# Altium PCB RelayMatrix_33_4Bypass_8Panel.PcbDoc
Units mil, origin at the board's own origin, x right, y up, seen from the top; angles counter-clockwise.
Board outline 13300 x 7975 mil, 4 copper layers (Top Layer, GND, Layer 1, Bottom Layer), stack 60.556 mil thick; 0 components, 0 nets, 45 pads, 0 vias.
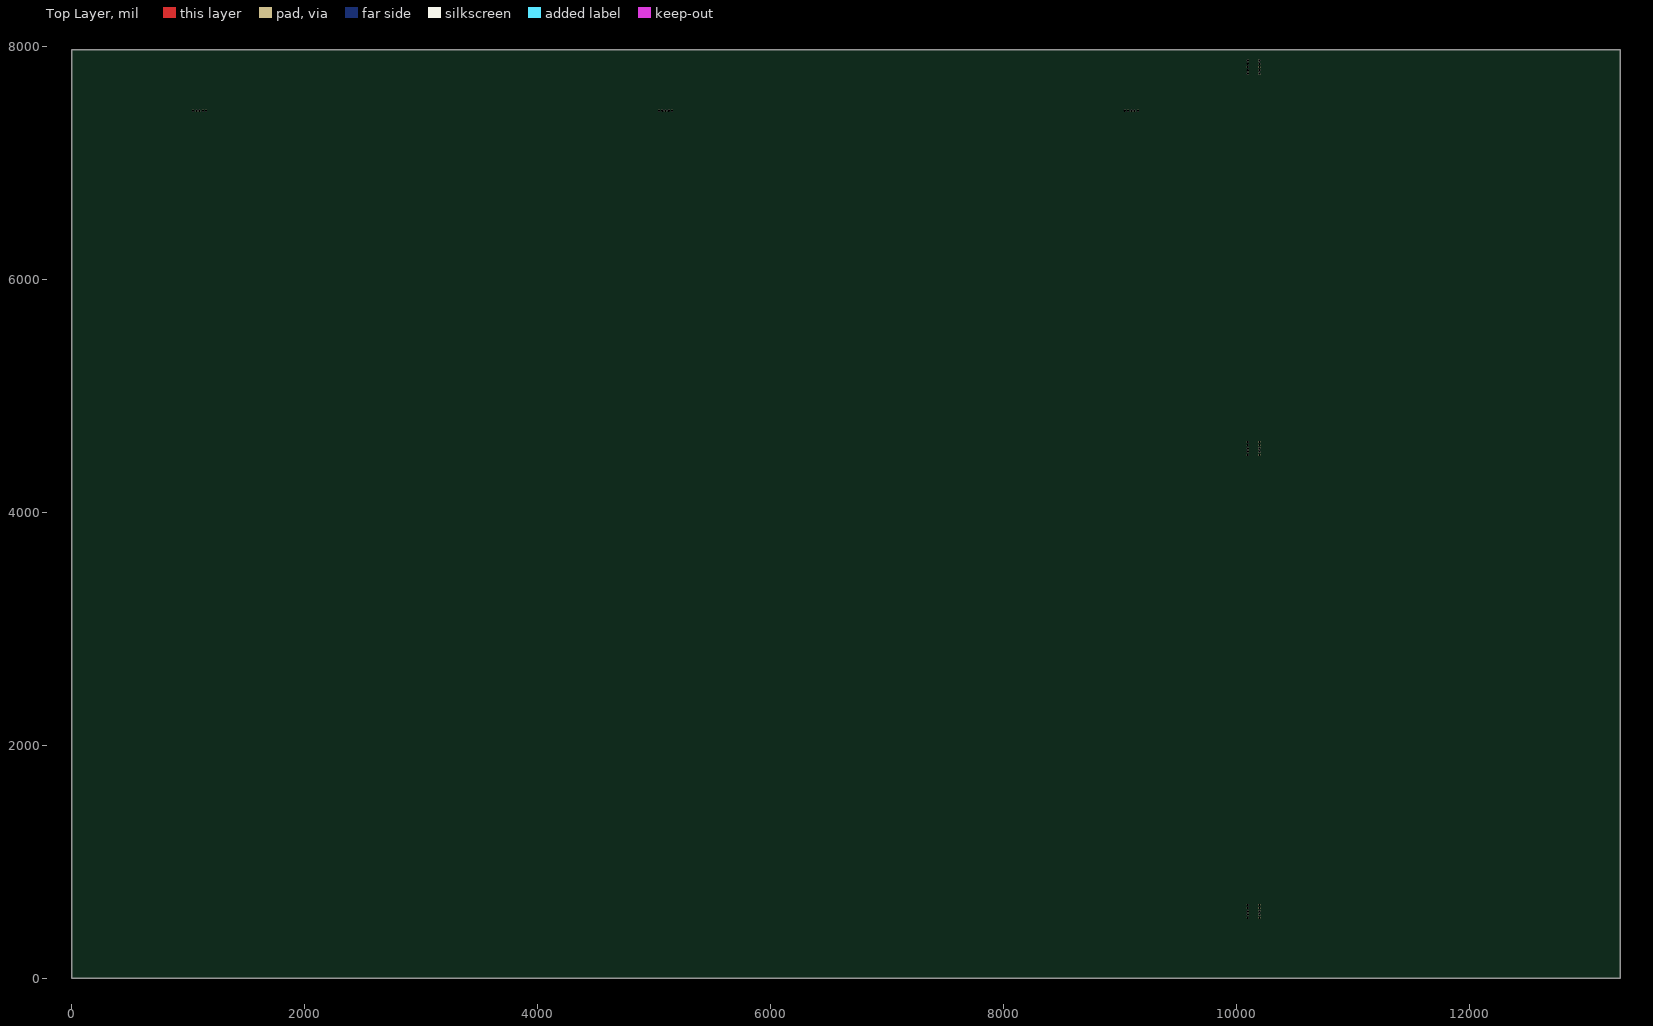
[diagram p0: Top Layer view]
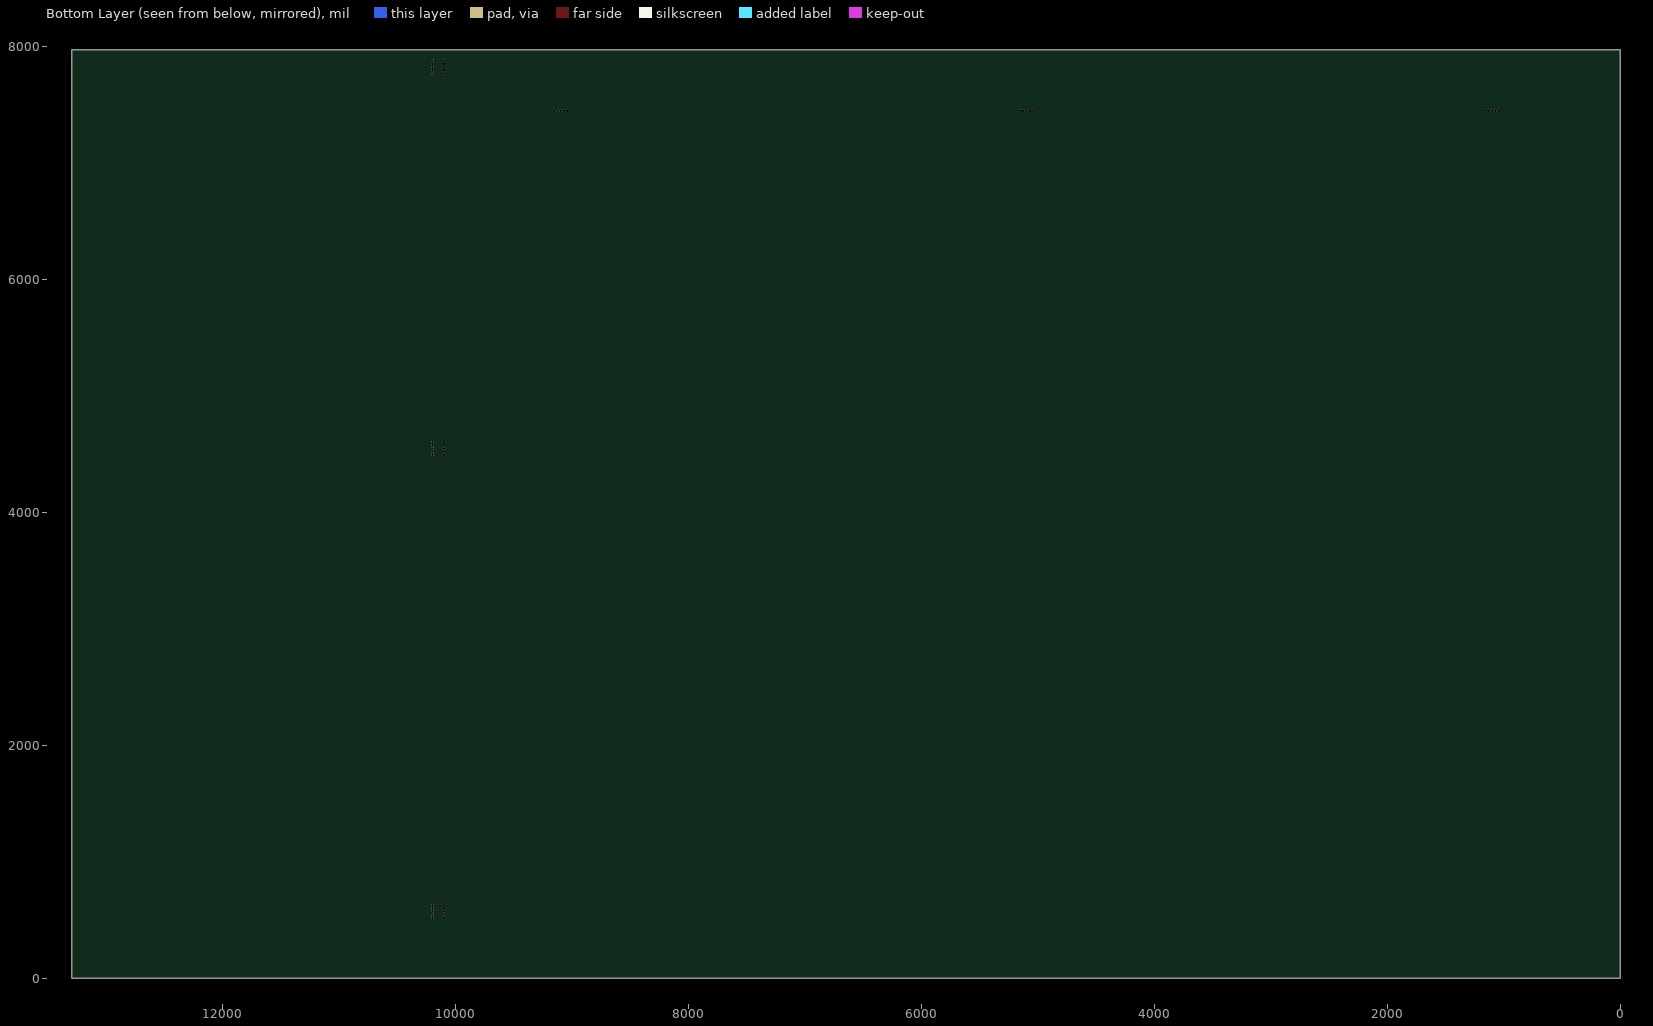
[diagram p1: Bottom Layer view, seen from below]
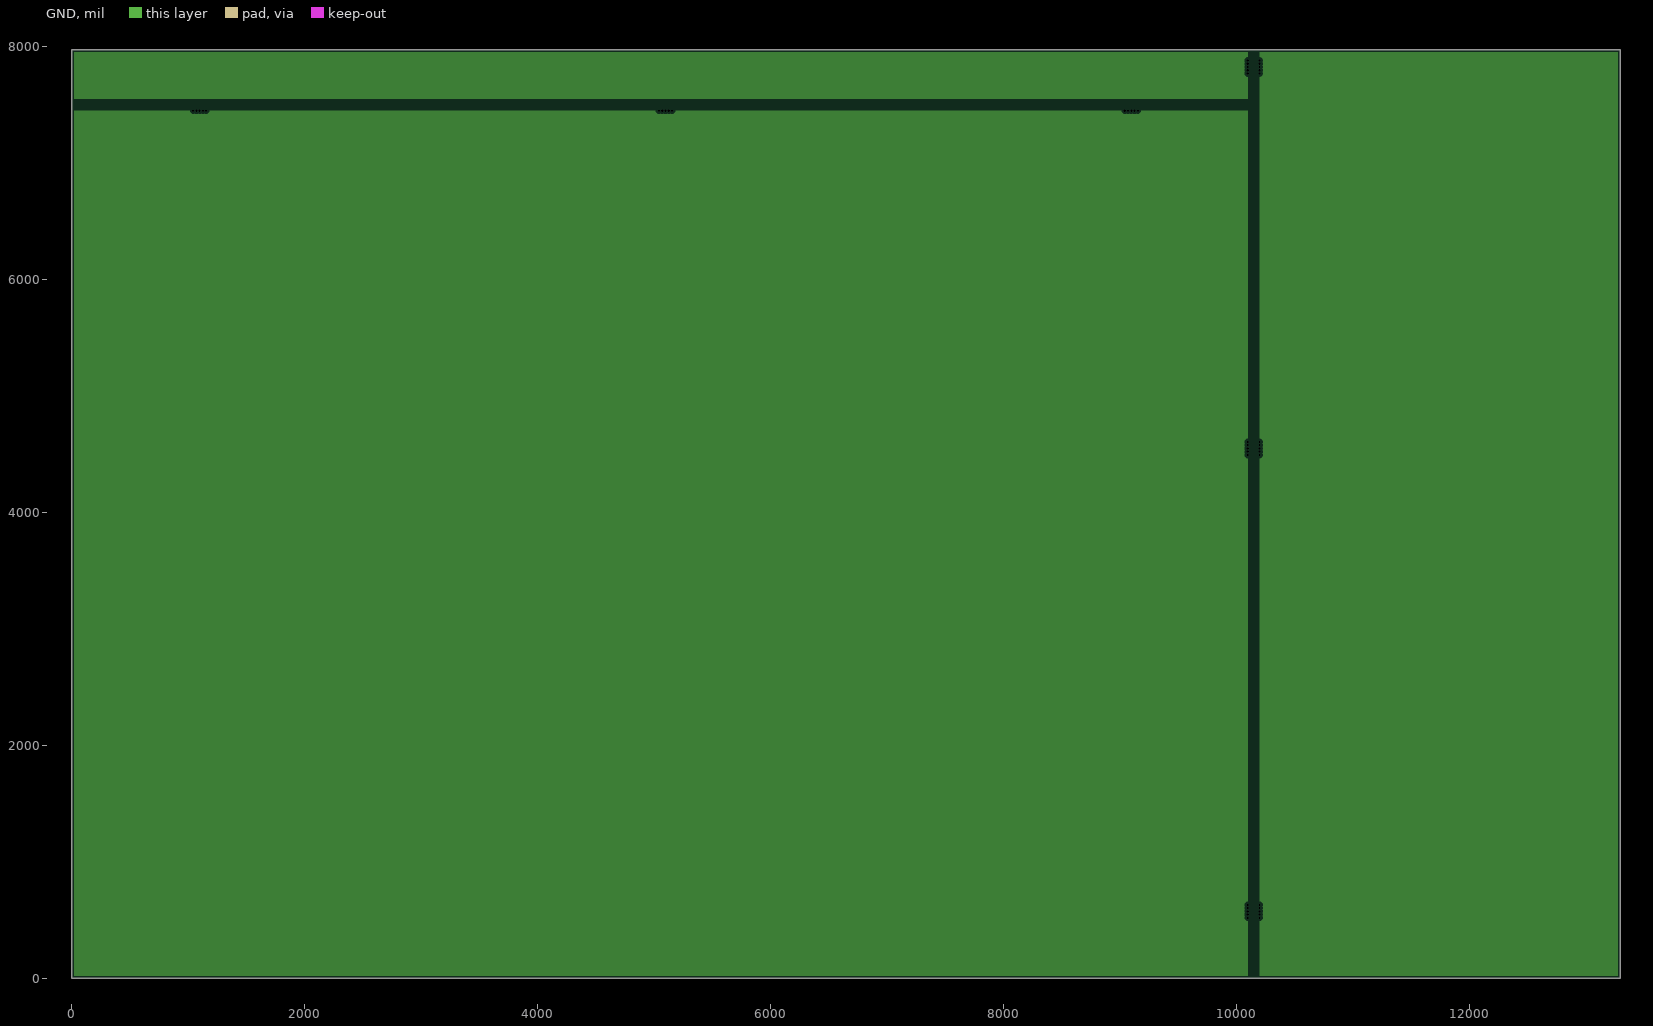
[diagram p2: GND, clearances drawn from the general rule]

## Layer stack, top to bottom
Top Solder: solder mask 0.4, Solder Resist, Dk 3.5
Top Layer: signal copper 1.4
Dielectric 2: prepreg 5, PP-006, Dk 4.1
GND: plane copper 1.378
Dielectric 1: dielectric 45, FR-4, Dk 4.8
Layer 1: signal copper 1.378
Dielectric 3: prepreg 5, PP-006, Dk 4.1
Bottom Layer: signal copper 1.4
Bottom Solder: solder mask 0.4, Solder Resist, Dk 3.5

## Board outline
0,0 13300,0 13300,7975 0,7975

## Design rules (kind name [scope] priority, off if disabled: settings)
Clearance [All] p1: gap=10 ignorepadtopadclearanceinfootprint=FALSE
PlaneClearance [All] p1: clearance=20
PlaneConnect [All] p1: planeconnectstyle=Relief reliefexpansion=20 reliefentries=4 reliefconductorwidth=10 reliefairgap=10
PolygonConnect [All] p1: connectstyle=Relief reliefconductorwidth=10 reliefentries=4 polygonreliefangle="90 Angle" airgapwidth=10
RoutingVias [All] p1: holewidth=28 width=50 viastyle="Through Hole" minholewidth=28 minwidth=50 maxholewidth=28 maxwidth=50
SolderMaskExpansion [All] p1: expansion=4 istentingtop=FALSE
Width [All] p1: maxlimit=10 minlimit=10 preferedwidth=10
28 further rules are at their usual default settings.

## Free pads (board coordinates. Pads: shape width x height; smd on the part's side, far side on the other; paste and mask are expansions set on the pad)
  round 18 hole 18 unplated mask+0: 0(1044,7450) 0(1072,7450) 0(1100,7450) 0(1128,7450) 0(1156,7450) 0(5044,7450) 0(5072,7450) 0(5100,7450) 0(5128,7450) 0(5156,7450) 0(9044,7450) 0(9072,7450) 0(9100,7450) 0(9128,7450) 0(9156,7450) 0(10100,519) 0(10100,547) 0(10100,575) 0(10100,603) 0(10100,631) 0(10100,4494) 0(10100,4522) 0(10100,4550) 0(10100,4578) 0(10100,4606) 0(10100,7769) 0(10100,7797) 0(10100,7825) 0(10100,7853) 0(10100,7881) 0(10200,519) 0(10200,547) 0(10200,575) 0(10200,603) 0(10200,631) 0(10200,4494) 0(10200,4522) 0(10200,4550) 0(10200,4578) 0(10200,4606) 0(10200,7769) 0(10200,7797) 0(10200,7825) 0(10200,7853) 0(10200,7881)

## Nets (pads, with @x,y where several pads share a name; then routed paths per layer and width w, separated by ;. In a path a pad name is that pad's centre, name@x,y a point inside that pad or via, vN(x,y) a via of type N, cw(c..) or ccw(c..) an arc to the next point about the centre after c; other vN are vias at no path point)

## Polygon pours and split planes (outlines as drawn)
no net on GND (split plane): 10099.92,7550.08 20.1,7550.08 20.1,7954.9 10099.92,7954.9
no net on GND (split plane): 13279.9,20.1 10200.08,20.1 10200.08,7954.9 13279.9,7954.9
no net on GND (split plane): 10099.92,20.1 20.1,20.1 20.1,7449.92 10099.92,7449.92

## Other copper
GND (plane layer: these items are gaps in the copper):
  lines w100: 0,7500 10150,7500 ; 10150,0 10150,7975

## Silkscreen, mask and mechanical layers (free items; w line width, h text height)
Mechanical 1:
  the board outline again, w10
Mechanical 2:
  lines w10: 0,0 10100,0 10100,7450 0,7450 0,0 ; 10200,0 13300,0 13300,8000 10200,8000 10200,0
Route Tool Path:
  lines w100: 0,7500 1000,7500 ; 1200,7500 5000,7500 ; 5200,7500 9000,7500 ; 9200,7500 10150,7500 ; 10150,0 10150,475 ; 10150,675 10150,4450 ; 10150,4650 10150,7725 ; 10150,7925 10150,7975
Drill Drawing:
  drawing of 189 lines, arcs and shapes, not listed
  text "Symbol" at 97.5,10952.5 h72
  text "Count" at 603.38,10952.5 h72
  text "Hole Size" at 1253.2,10952.5 h72
  text "Plated" at 2402.86,10952.5 h72
  text "Hole Type" at 2908.74,10952.5 h72
  text "Drill Layer Pair" at 3642.54,10952.5 h72
  text "Via/Pad" at 5142.09,10952.5 h72
  text "Pad Shape" at 5731.94,10952.5 h72
  text "Template" at 6477.74,10952.5 h72
  text "Description" at 7167.55,10952.5 h72
  text "Hole Tolerance (+)" at 8021.32,10952.5 h72
  text "Hole Tolerance (-)" at 9354.92,10952.5 h72
  text "2" at 603.38,10802.5 h60
  text "28.00mil (0.711mm)" at 1253.2,10802.5 h60
  text "PTH" at 2402.86,10802.5 h60
  text "Round" at 2908.74,10802.5 h60
  text "Top Layer - Bottom Layer" at 3642.54,10802.5 h60
  text "Via" at 5142.09,10802.5 h60
  text "Rounded" at 5731.94,10802.5 h60
  text "v127h71" at 6477.74,10802.5 h60
  text "A" at 68.41,10792.51 h66.67
  text "2" at 603.38,10652.5 h60
  text "109.06mil (2.770mm)" at 1253.2,10652.5 h60
  text "PTH" at 2402.86,10652.5 h60
  text "Round" at 2908.74,10652.5 h60
  text "Top Layer - Bottom Layer" at 3642.54,10652.5 h60
  text "Pad" at 5142.09,10652.5 h60
  text "Rounded" at 5731.94,10652.5 h60
  text "c455h277" at 6477.74,10652.5 h60
  text "2" at 603.38,10502.5 h60
  text "125.20mil (3.180mm)" at 1253.2,10502.5 h60
  text "PTH" at 2402.86,10502.5 h60
  text "Round" at 2908.74,10502.5 h60
  text "Top Layer - Bottom Layer" at 3642.54,10502.5 h60
  text "Pad" at 5142.09,10502.5 h60
  text "Rounded" at 5731.94,10502.5 h60
  text "c480h318" at 6477.74,10502.5 h60
  text "3" at 603.38,10352.5 h60
  text "80.00mil (2.032mm)" at 1253.2,10352.5 h60
  text "PTH" at 2402.86,10352.5 h60
  text "Round" at 2908.74,10352.5 h60
  text "Top Layer - Bottom Layer" at 3642.54,10352.5 h60
  text "Pad" at 5142.09,10352.5 h60
  text "(Mixed)" at 5731.94,10352.5 h60
  text "(Mixed)" at 6477.74,10352.5 h60
  text "5" at 603.38,10202.5 h60
  text "193.00mil (4.902mm)" at 1253.2,10202.5 h60
  text "PTH" at 2402.86,10202.5 h60
  text "Round" at 2908.74,10202.5 h60
  text "Top Layer - Bottom Layer" at 3642.54,10202.5 h60
  text "Pad" at 5142.09,10202.5 h60
  text "Rounded" at 5731.94,10202.5 h60
  text "c584h490" at 6477.74,10202.5 h60
  text "6" at 603.38,10052.5 h60
  text "38.98mil (0.990mm)" at 1253.2,10052.5 h60
  text "PTH" at 2402.86,10052.5 h60
  text "Round" at 2908.74,10052.5 h60
  text "Top Layer - Bottom Layer" at 3642.54,10052.5 h60
  text "Pad" at 5142.09,10052.5 h60
  text "Rounded" at 5731.94,10052.5 h60
  text "c154h99" at 6477.74,10052.5 h60
  text "10" at 603.38,9902.5 h60
  text "130.00mil (3.302mm)" at 1253.2,9902.5 h60
  text "PTH" at 2402.86,9902.5 h60
  text "Round" at 2908.74,9902.5 h60
  text "Top Layer - Bottom Layer" at 3642.54,9902.5 h60
  text "Pad" at 5142.09,9902.5 h60
  text "Rounded" at 5731.94,9902.5 h60
  text "c635h330" at 6477.74,9902.5 h60
  text "16" at 603.38,9752.5 h60
  text "39.37mil (1.000mm)" at 1253.2,9752.5 h60
  text "PTH" at 2402.86,9752.5 h60
  text "Round" at 2908.74,9752.5 h60
  text "Top Layer - Bottom Layer" at 3642.54,9752.5 h60
  text "Pad" at 5142.09,9752.5 h60
  text "(Mixed)" at 5731.94,9752.5 h60
  text "(Mixed)" at 6477.74,9752.5 h60
  text "20" at 603.38,9602.5 h60
  text "65.00mil (1.651mm)" at 1253.2,9602.5 h60
  text "PTH" at 2402.86,9602.5 h60
  text "Round" at 2908.74,9602.5 h60
  text "Top Layer - Bottom Layer" at 3642.54,9602.5 h60
  text "Pad" at 5142.09,9602.5 h60
  text "Rounded" at 5731.94,9602.5 h60
  text "c216h165" at 6477.74,9602.5 h60
  text "22" at 603.38,9452.5 h60
  text "62.21mil (1.580mm)" at 1253.2,9452.5 h60
  text "PTH" at 2402.86,9452.5 h60
  text "Round" at 2908.74,9452.5 h60
  text "Top Layer - Bottom Layer" at 3642.54,9452.5 h60
  text "Pad" at 5142.09,9452.5 h60
  text "Rounded" at 5731.94,9452.5 h60
  text "c254h158" at 6477.74,9452.5 h60
  text "26" at 603.38,9302.5 h60
  text "128.35mil (3.260mm)" at 1253.2,9302.5 h60
  text "PTH" at 2402.86,9302.5 h60
  text "Round" at 2908.74,9302.5 h60
  text "Top Layer - Bottom Layer" at 3642.54,9302.5 h60
  text "Pad" at 5142.09,9302.5 h60
  text "Rounded" at 5731.94,9302.5 h60
  text "(Mixed)" at 6477.74,9302.5 h60
  text "45" at 603.38,9152.5 h60
  text "18.00mil (0.457mm)" at 1253.2,9152.5 h60
  text "NPTH" at 2402.86,9152.5 h60
  text "Round" at 2908.74,9152.5 h60
  text "Top Layer - Bottom Layer" at 3642.54,9152.5 h60
  text "Pad" at 5142.09,9152.5 h60
  text "Rounded" at 5731.94,9152.5 h60
  text "c46hn46m46" at 6477.74,9152.5 h60
  text "B" at 68.41,9142.51 h66.67
  text "50" at 603.38,9002.5 h60
  text "40.16mil (1.020mm)" at 1253.2,9002.5 h60
  text "PTH" at 2402.86,9002.5 h60
  text "Round" at 2908.74,9002.5 h60
  text "Top Layer - Bottom Layer" at 3642.54,9002.5 h60
  text "Pad" at 5142.09,9002.5 h60
  text "(Mixed)" at 5731.94,9002.5 h60
  text "(Mixed)" at 6477.74,9002.5 h60
  text "68" at 603.38,8852.5 h60
  text "30.00mil (0.762mm)" at 1253.2,8852.5 h60
  text "PTH" at 2402.86,8852.5 h60
  text "Round" at 2908.74,8852.5 h60
  text "Top Layer - Bottom Layer" at 3642.54,8852.5 h60
  text "Pad" at 5142.09,8852.5 h60
  text "Rounded" at 5731.94,8852.5 h60
  text "c127h76" at 6477.74,8852.5 h60
  text "96" at 603.38,8702.5 h60
  text "10.00mil (0.254mm)" at 1253.2,8702.5 h60
  text "PTH" at 2402.86,8702.5 h60
  text "Round" at 2908.74,8702.5 h60
  text "Top Layer - Bottom Layer" at 3642.54,8702.5 h60
  text "Via" at 5142.09,8702.5 h60
  text "Rounded" at 5731.94,8702.5 h60
  text "v76h25" at 6477.74,8702.5 h60
  text "194" at 603.38,8552.5 h60
  text "42.91mil (1.090mm)" at 1253.2,8552.5 h60
  text "PTH" at 2402.86,8552.5 h60
  text "Round" at 2908.74,8552.5 h60
  text "Top Layer - Bottom Layer" at 3642.54,8552.5 h60
  text "Pad" at 5142.09,8552.5 h60
  text "(Mixed)" at 5731.94,8552.5 h60
  text "(Mixed)" at 6477.74,8552.5 h60
  text "941" at 603.38,8402.5 h60
  text "15.00mil (0.381mm)" at 1253.2,8402.5 h60
  text "PTH" at 2402.86,8402.5 h60
  text "Round" at 2908.74,8402.5 h60
  text "Top Layer - Bottom Layer" at 3642.54,8402.5 h60
  text "Via" at 5142.09,8402.5 h60
  text "Rounded" at 5731.94,8402.5 h60
  text "(Mixed)" at 6477.74,8402.5 h60
  text "1508 Total" at 603.38,8252.5 h60

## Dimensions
0,0 to 13300,0 on Dimension
10200,0 to 13300,0 on Dimension
0,0 to 10100,0 on Dimension
0,0 to 0,7450 on Dimension
0,7975 to 0,0 on Dimension

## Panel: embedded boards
"..\RelayBypass_8\RelayBypass8.PcbDoc" at 13300,0, 1 rows x 1 columns, spacing 2500 x 1500, rotation 90
"..\RelayMatrix_33_4\RelayMatrix334.PcbDoc" at 0,0, 1 rows x 1 columns, spacing 2500 x 1500, rotation 0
